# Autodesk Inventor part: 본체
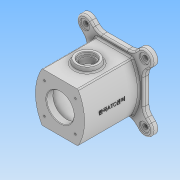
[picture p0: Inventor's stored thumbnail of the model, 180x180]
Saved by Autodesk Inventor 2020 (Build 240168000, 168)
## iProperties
Created: 2022-01
Part Number: 본체
Material: 일반
Document SubType Name: Modeling
Designer: user
Density: 1 g/cm^3
Appearance: 기본값
Author: user
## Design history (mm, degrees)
sketch "스케치1"
  geometry: L1 (-32.942, 45)-(32.942, 45); L2 (32.942, -45)-(-32.942, -45); L3 (-45, 45)-(45, -45); L4 (45, 45)-(-45, -45); A1 r 90 centre (45, 0) between (-32.942, 45) and (-32.942, -45); A2 r 90 centre (-45, 0) between (32.942, -45) and (32.942, 45); 2 further points
  constraints: 8 end point, 6 point on circle, 2 centre point, 2 midpoint, 2 vertical alignment, 1 horizontal, 1 parallel, 1 perpendicular
  dimensions: "d4" = 90 radius of A1; "d5" = 90 radius of A2; "d6" = 90 distance between parallel lines of L2 L1; "d7" = 45 deg angle of L3 L1; "d8" = 45 distance from line of point (0, 0) L1; "d9" = 0 distance from line of L4.start L1; "d10" = 31.81981 distance from line of A1.centre L3; "d11" = 0 distance from line of L3.start L1
extrude "돌출1" new body sketch "스케치1" stored distance "d2" = 100; taper "d3" = 0 deg
sketch "스케치2"
  geometry: L1 (-53, 53)-(53, 53); L2 (53, 53)-(53, -53); L3 (53, -53)-(-53, -53); L4 (-53, -53)-(-53, 53); L5 (-53, 53)-(53, -53); L6 (53, 53)-(-53, -53); L7 (-53, 53)-(53, -53); L8 (53, 53)-(-53, -53); L9 (-54.447, -54.447)-(54.447, 54.447); L10 (-43.841, -65.054)-(65.054, 43.841); L11 (43.841, 65.054)-(-65.054, -43.841); L12 (54.447, -54.447)-(-54.447, 54.447); L13 (65.054, -43.841)-(-43.841, 65.054); L14 (-65.054, 43.841)-(43.841, -65.054); A1 r 15 centre (-54.447, -54.447) between (-65.054, -43.841) and (-43.841, -65.054); A2 r 15 centre (54.447, 54.447) between (65.054, 43.841) and (43.841, 65.054); A3 r 15 centre (54.447, -54.447) between (43.841, -65.054) and (65.054, -43.841); A4 r 15 centre (-54.447, 54.447) between (-43.841, 65.054) and (-65.054, 43.841); 10 further points
  constraints: 36 end point, 8 midpoint, 8 point on circle, 8 tangent, 6 equal length, 4 centre point, 2 perpendicular, 1 horizontal, 1 point on line
  dimensions: "d12" = 106 distance of L2.end L3.end; "d13" = 106 distance of L1.end L2.end; "d102" = 154 distance of L12.start L12.end; "d103" = 154 distance of L9.start L9.end; "d104" = 30 distance between parallel lines of L13 L14; "d105" = 30 distance between parallel lines of L11 L10
sketch "스케치3"
  geometry: C1 r 25 at (0, 0); 1 further point
  constraints: 1 centre point, 1 coincident
  dimensions: "d18" = 50 diameter of C1
extrude "돌출3" cut sketch "스케치3" distance "d19" = 12; taper "d20" = 0 deg
sketch "스케치4"
  geometry: C1 r 37 at (0, 0); 1 further point
  constraints: 1 centre point, 1 coincident
  dimensions: "d21" = 74 diameter of C1
extrude "돌출4" cut sketch "스케치4" distance "d22" = 86; taper "d23" = 0 deg
node "작업 평면4"
sketch "스케치5"
  geometry: C1 r 25 at (0, 0); 1 further point
  constraints: 1 centre point, 1 coincident
  dimensions: "d24" = 50 diameter of C1
extrude "돌출5" cut sketch "스케치5" distance "d25" = 12; taper "d26" = 0 deg
node "작업 평면1"
sketch "스케치6"
  geometry: L1 (42.393, -60)-(68, -60) reference; C1 r 20 at (0, 0); 2 further points
  constraints: 1 centre point
  dimensions: "d28" = 40 diameter of C1; "d29" = 60 distance from line of L1 C1.centre
extrude "돌출6" join sketch "스케치6" stored distance "d30" = 12; taper "d31" = 15 deg
sketch "스케치7"
  geometry: C1 r 20 at (0, 0) reference; 2 further points
  constraints: 1 coincident
hole "구멍1" sketch "스케치7" at (0, 0) diameter "d32" = 30; stored, may be unused: countersink angle "d36" = 90 deg, drill point angle "d38" = 0 deg; dims "d33" = 6, "d34" = 4, "d35" = 2, "d37" = 5
sketch "스케치8"
  geometry: C1 r 15 at (0, 0) reference; 2 further points
  constraints: 1 coincident
hole "구멍2" sketch "스케치8" at (0, 0) diameter "d39" = 24; stored, may be unused: countersink angle "d43" = 90 deg, drill point angle "d45" = 0 deg; dims "d40" = 6, "d41" = 4, "d42" = 2, "d44" = 28.75
sketch "스케치9"
  geometry: L1 (0, 0)-(-66.832, 66.832); L2 (0, 0)-(74.356, 74.356); L3 (0, 0)-(0, 91); L4 (0, 0)-(-78.259, -78.259); L5 (0, 0)-(0, -96); L6 (0, 0)-(78.186, -78.186); C1 r 25 at (0, 0) reference; A1 r 40 centre (0, 0) between (-28.284, 28.284) and (28.284, 28.284); 3 further points
  constraints: 12 end point, 4 point on circle, 4 point on line, 2 vertical, 1 centre point, 1 coincident
  dimensions: "d46" = 80 diameter of A1; "d47" = 45 deg angle of L1 L3; "d48" = 45 deg angle of L2 L3; "d49" = 45 deg angle of L6 L5; "d50" = 45 deg angle of L4 L5
hole "구멍3" sketch "스케치9" at (-28.284, 28.284), (28.284, 28.284), (-28.284, -28.284), (28.284, -28.284) diameter "d51" = 3.242; stored, may be unused: countersink angle "d55" = 90 deg, drill point angle "d57" = 118 deg; dims "d52" = 8, "d53" = 4, "d54" = 2, "d56" = 10
node "작업 평면3"
sketch "스케치10"
  geometry: L1 (0, 0)-(0, 94); L2 (0, 0)-(0, -91); L3 (0, 0)-(-79.85, 79.85); L4 (0, 0)-(83.8, 83.8); L5 (0, 0)-(88.896, -88.896); L6 (0, 0)-(-75.611, -75.611); C1 r 25 at (0, 0) reference; C2 r 40 at (0, 0); C3 r 1.621 at (-28.284, 28.284) reference; C4 r 1.621 at (28.284, 28.284) reference; C5 r 1.621 at (28.284, -28.284) reference; 5 further points
  constraints: 12 end point, 4 coincident, 2 vertical, 1 centre point, 1 point on line
  dimensions: "d58" = 80 diameter of C2; "d59" = 45 deg angle of L1 L3; "d60" = 45 deg angle of L4 L1; "d62" = 45 deg angle of L2 L5; "d63" = 45 deg angle of L2 L6
hole "구멍4" sketch "스케치10" at (-28.284, 28.284), (28.284, 28.284), (-28.841, -28.841), (28.284, -28.284) diameter "d64" = 3.242; stored, may be unused: countersink angle "d68" = 90 deg, drill point angle "d70" = 118 deg; dims "d65" = 8, "d66" = 4, "d67" = 2, "d69" = 10
node "작업 평면2"
sketch "스케치11"
  geometry: L1 (0, 0)-(0, 104); L2 (0, 0)-(-87.57, 87.57); L3 (0, 0)-(74.542, 74.542); L4 (0, 0)-(76.867, -76.867); L5 (0, 0)-(-76.371, -76.371); L6 (0, 0)-(0, -101); A1 r 77 centre (0, 0) between (-54.447, 54.447) and (54.447, 54.447); 3 further points
  constraints: 12 end point, 4 point on circle, 4 point on line, 2 vertical, 1 centre point, 1 coincident
  dimensions: "d71" = 154 diameter of A1; "d72" = 45 deg angle of L2 L1; "d73" = 45 deg angle of L3 L1; "d74" = 45 deg angle of L6 L4; "d75" = 45 deg angle of L6 L5
hole "구멍5" sketch "스케치11" at (-54.447, 54.447), (54.447, 54.447), (54.447, -54.447), (-54.447, -54.447) diameter "d76" = 18; stored, may be unused: countersink angle "d80" = 90 deg, drill point angle "d82" = 0 deg; dims "d77" = 8, "d78" = 4, "d79" = 2, "d81" = 2
node "작업 평면5"
sketch "스케치12"
  geometry: A1 r 9 centre (0, 0) between (-5.258, -7.304) and (5.258, -7.304) reference; A2 r 9 centre (-77, -77) between (-69.696, -82.258) and (-69.696, -71.742) reference; A3 r 9 centre (0, -154) between (5.258, -146.696) and (-5.258, -146.696) reference; A4 r 9 centre (77, -77) between (69.696, -71.742) and (69.696, -82.258) reference; 5 further points
  constraints: 4 coincident
hole "구멍6" sketch "스케치12" at (0, 0), (-77, -77), (0, -154), (77, -77) diameter "d83" = 9; stored, may be unused: countersink angle "d87" = 90 deg, drill point angle "d89" = 0 deg; dims "d84" = 8, "d85" = 4, "d86" = 2, "d88" = 2
sketch "스케치13"
  geometry: L1 (23.503, -60)-(37.645, -60) reference; L2 (53, 15)-(53, -15) reference; 2 further points
  constraints: 1 other
  dimensions: "d91" = 60 distance from line of L1 point (0, 0); "d92" = 53 distance from line of point (0, 0) L2
feature "엠보싱1" sketch "스케치13" dims "d4" = 90, "d5" = 90, "d6" = 90, "d7" = 45 deg, "d8" = 45, "d9" = 0, "d10" = 31.81981, "d11" = 0, "d12" = 106, "d13" = 106, "d93" = 0.5, "d94" = 0, "d102" = 154, "d103" = 154, "d104" = 30, "d105" = 30
chamfer "모따기1" distance "d95" = 1; stored, may be unused: second distance "d96" = 2, angle "d97" = 45 deg
fillet "모깎기2" dims "d98" = 3
fillet "모깎기3" dims "d99" = 3
fillet "모깎기4" dims "d100" = 3
extrude "돌출7" join sketch "스케치2" distance "d106" = 10; taper "d107" = 0 deg
sketch "스케치14"
  geometry: A1 r 15 centre (-54.447, 54.447) between (-43.841, 65.054) and (-65.054, 43.841) reference; A2 r 15 centre (54.447, 54.447) between (65.054, 43.841) and (43.841, 65.054) reference; A3 r 15 centre (54.447, -54.447) between (43.841, -65.054) and (65.054, -43.841) reference; A4 r 15 centre (-54.447, -54.447) between (-65.054, -43.841) and (-43.841, -65.054) reference; 5 further points
  constraints: 4 coincident
hole "구멍7" sketch "스케치14" at (-54.447, 54.447), (54.447, 54.447), (54.447, -54.447), (-54.447, -54.447) diameter "d108" = 18; stored, may be unused: countersink angle "d112" = 90 deg, drill point angle "d114" = 0 deg; dims "d109" = 8, "d110" = 4, "d111" = 2, "d113" = 2
sketch "스케치15"
  geometry: C1 r 9 at (0, 0) reference; C2 r 9 at (0, -108.894) reference; C3 r 9 at (108.894, -108.894) reference; C4 r 9 at (108.894, 0) reference; 5 further points
  constraints: 4 coincident
hole "구멍8" sketch "스케치15" at (0, 0), (0, -108.894), (108.894, -108.894), (108.894, 0) diameter "d115" = 9; stored, may be unused: countersink angle "d119" = 90 deg, drill point angle "d121" = 0 deg; dims "d116" = 8, "d117" = 4, "d118" = 2, "d120" = 2
fillet "모깎기6" dims "d122" = 20
fillet "모깎기7" dims "d123" = 3
fillet "모깎기8" dims "d124" = 3
sketch "스케치16"
  geometry: C1 r 25 at (0, 0); 1 further point
  constraints: 1 centre point, 1 coincident
  dimensions: "d125" = 50 diameter of C1
extrude "돌출8" cut sketch "스케치16" distance "d126" = 10; taper "d127" = 0 deg
chamfer "모따기2" distance "d128" = 1; stored, may be unused: second distance "d129" = 2, angle "d130" = 45 deg
sketch "스케치17"
  geometry: L1 (0, 0)-(0, 92); L2 (0, 0)-(-89.051, 89.051); L3 (0, 0)-(78.026, 78.026); L4 (0, 0)-(87.144, -87.144); L5 (0, 0)-(-86.917, -86.917); L6 (0, 0)-(0, -92); C1 r 1.621 at (-28.841, -28.841) reference; C2 r 1.621 at (28.284, -28.284) reference; A1 r 40 centre (0, 0) between (-29.407, 27.115) and (28.284, 28.284); 3 further points
  constraints: 12 end point, 3 coincident, 2 point on circle, 2 vertical, 1 centre point, 1 point on line, 2 other
  dimensions: "d131" = 45 deg angle of L1 L2; "d132" = 45 deg angle of L3 L1; "d133" = 45 deg angle of L6 L4; "d134" = 45 deg angle of L6 L5; "d135" = 80 diameter of A1
hole "구멍9" sketch "스케치17" at (-29.407, 27.115), (28.284, 28.284), (-28.841, -28.841), (28.284, -28.284) diameter "d136" = 3.242; stored, may be unused: countersink angle "d140" = 90 deg, drill point angle "d142" = 118 deg; dims "d137" = 8, "d138" = 4, "d139" = 2, "d141" = 10
node "솔리드1"
feature "A9D066F2-1C7D-4E18-AEED-F7BC21143FA4" dims "d32" = 30, "d33" = 6, "d34" = 4, "d35" = 2, "d36" = 90 deg, "d37" = 5, "d38" = 0
other parameters: "d27" = 53
